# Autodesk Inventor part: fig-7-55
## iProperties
Shininess: 77.0
Length Units: 11269
Angle Units: 11279
Time Units: 11290
Mass Units: 11283
Length Display Precision: 3
Angle Display Precision: 2
Created: 2002-01
Part Number: fig-7-55
Document SubType Name: Modeling
Designer: ***
Density: 0.0
Volumn: 0.0
Area: 0.0
PropertySet Name: Model Information
Control State: 0
Master: False
Checked Out: False
Author: ***
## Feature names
1. Extrusion2
2. Split4
